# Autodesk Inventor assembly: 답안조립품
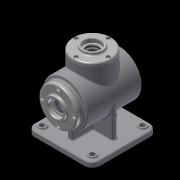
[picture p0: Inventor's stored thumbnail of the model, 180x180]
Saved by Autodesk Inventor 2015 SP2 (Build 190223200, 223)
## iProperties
Created: 2015-07
Part Number: 답안조립품
Document SubType Name: Assembly
Designer: AMC
Author: AMC
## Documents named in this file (4)
- C:\Users\AMC\Desktop\450705V1025\답안조립품.iam
- C:\Users\AMC\Desktop\450705V1025\본체.ipt
- C:\Users\AMC\Desktop\450705V1025\커버.ipt
- C:\Users\AMC\Desktop\450705V1025\베어링 6203.ipt
